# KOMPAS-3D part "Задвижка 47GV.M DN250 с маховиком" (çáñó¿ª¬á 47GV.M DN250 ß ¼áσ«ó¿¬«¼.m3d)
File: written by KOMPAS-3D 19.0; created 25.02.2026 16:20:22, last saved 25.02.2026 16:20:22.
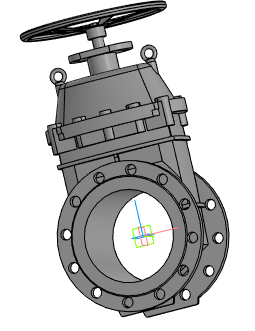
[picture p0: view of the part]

Document properties: Автор: Евгений; Полное имя файла: ..\..\47GVM\DR.47GVM.250.16.00.000\DR.47GVM.250.16.00.00 - Задвижка с обрезиненным клином DN250.a3d

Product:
- Part/product: Задвижка 47GV.M DN250 с маховиком
    Масса: 158.133
    source file: 47GV.M DN250\DR.47GVM.250.16.00.00 - Задвижка с обрезиненным клином DN250.spw
  - Component: Задвижка с обрезиненным клином DN250. Сборочный чертеж  | designation DR.47GVM.250.16.00.00СБ  | pos. 0  | Масса: 79.6129; Раздел спецификации: Документация; Форматы листов документа: 2xA3; source file: 47GV.M DN250\DR.47GVM.250.16.00.000 СБ - Задвижка с обрезиненным клином DN250.cdw

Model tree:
1. Операция без истории:1

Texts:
  Точка начала. Х
  Точка начала. Y
  Точка начала. Z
